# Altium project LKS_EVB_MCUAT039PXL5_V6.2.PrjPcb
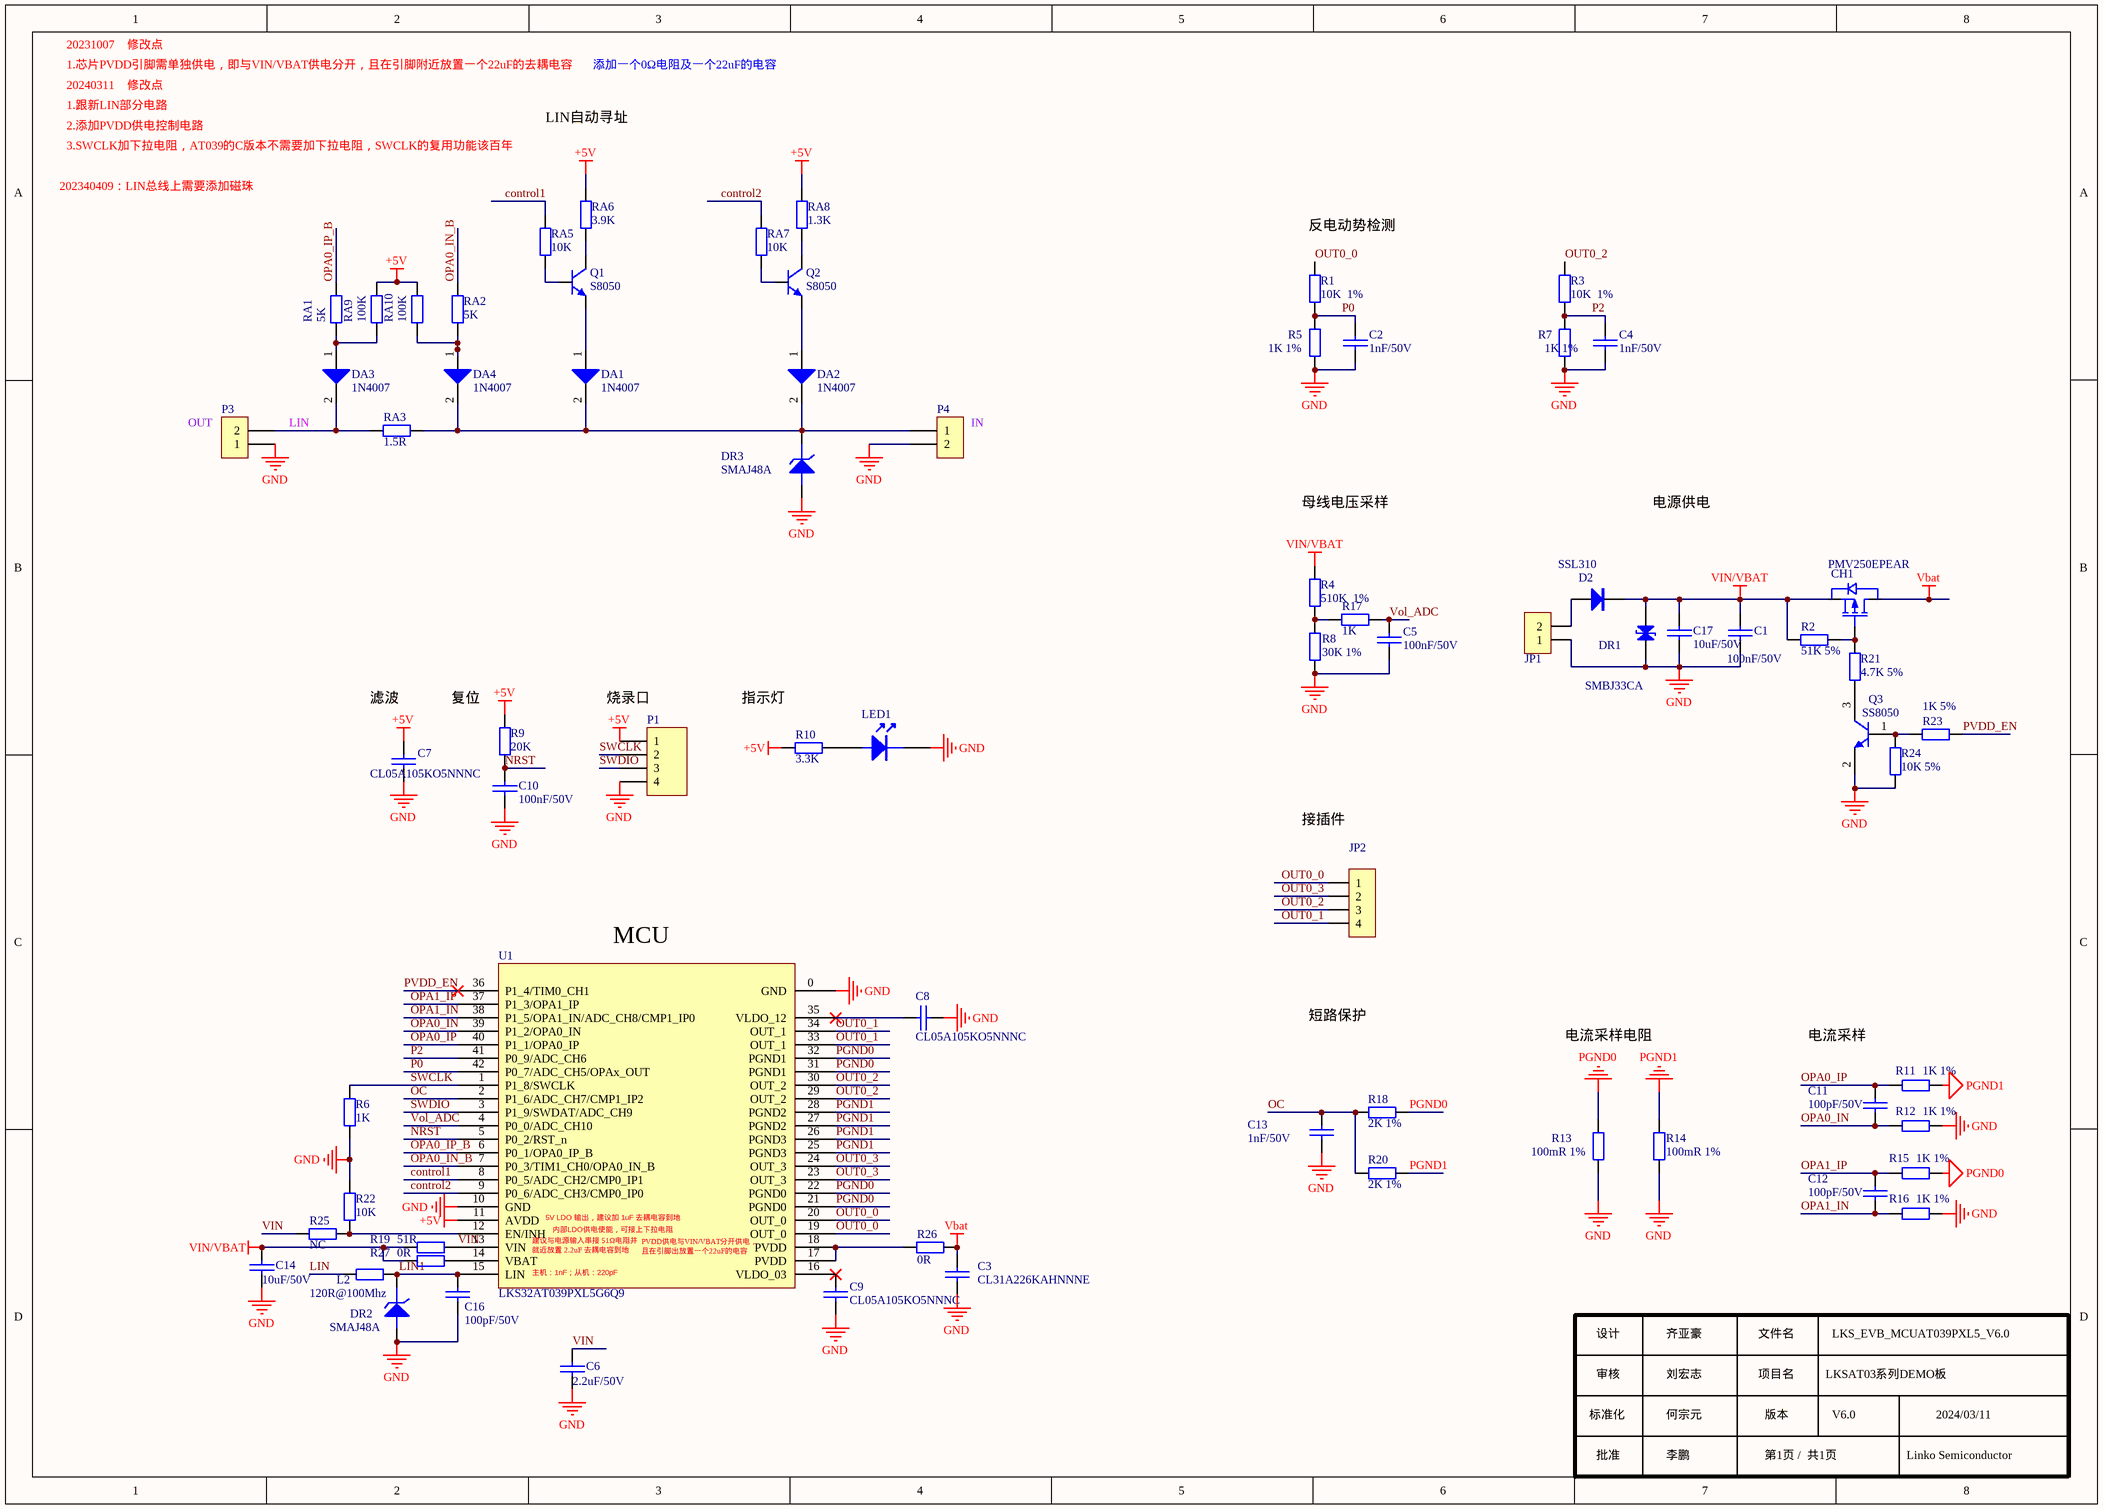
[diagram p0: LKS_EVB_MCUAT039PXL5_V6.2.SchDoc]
1 sheet, 72 parts. Net scope: global (net labels, ports and power ports of the same name join across sheets).
Board file: LKS_EVB_MCUAT039PXL5_V6.2.PcbDoc

## Sheet LKS_EVB_MCUAT039PXL5_V6.2.SchDoc
size A3; SheetNumber: 1; SheetTotal: 1

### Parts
C1  100nF/50V  [0805C]
C2  1nF/50V  [0603C]
C3  CL31A226KAHNNNE  [1206C]
C4  1nF/50V  [0603C]
C5  100nF/50V  [0603C]
C6  2.2uF/50V  [0805C]
C7  CL05A105KO5NNNC  [0402C]
C8  CL05A105KO5NNNC  [0402C]
C9  CL05A105KO5NNNC  [0402C]
C10  100nF/50V  [0603C]
C11  100pF/50V  [0603C]
C12  100pF/50V  [0603C]
C13  1nF/50V  [0603C]
C14  10uF/50V  [0805C]
C16  100pF/50V  [0603C]
C17  10uF/50V  [0805C]
CH1  PMV250EPEAR  [SOT-23]
D2  SSL310  [SMA]
DA1  1N4007  [SOD-323]
DA2  1N4007  [SOD-323]
DA3  1N4007  [SOD-323]
DA4  1N4007  [SOD-323]
DR1  SMBJ33CA  [SMB]
DR2  SMAJ48A  [SMA]
DR3  SMAJ48A  [SMA]
JP1  B2P-VH(LF)(SN)  [HT3.96-LI-2P]  (value not drawn)
JP2  HDR-1X4  [HDR 1X4]  (value not drawn)
L2  120R@100Mhz  [0603R]
LED1  LED  [LED 0603G]  (value not drawn)
P1  HDR-1X4  [HDR 1X4]  (value not drawn)
P3  1X2  [HDR 1X2]  (value not drawn)
P4  1X2  [HDR 1X2]  (value not drawn)
Q1  S8050  [SOT-23]
Q2  S8050  [SOT-23]
Q3  SS8050  [SOT-23]
R1  10K  1%  [0603R]
R2  51K 5%  [0402R]
R3  10K  1%  [0603R]
R4  510K  1%  [0603R]
R5  1K 1%  [0603R]
R6  1K  [0603R]
R7  1K 1%  [0603R]
R8  30K 1%  [0603R]
R9  20K  [0603R]
R10  3.3K  [0603R]
R11  1K 1%  [0603R]
R12  1K 1%  [0603R]
R13  100mR 1%  [1206R]
R14  100mR 1%  [1206R]
R15  1K 1%  [0603R]
R16  1K 1%  [0603R]
R17  1K  [0603R]
R18  2K 1%  [0603R]
R19  51R  [0603R]
R20  2K 1%  [0603R]
R21  4.7K 5%  [0402R]
R22  10K  [0603C _1]
R23  1K 5%  [0402R]
R24  10K 5%  [0402R]
R25  NC  [0603C _1]
R26  0R  [0603R]
R27  0R  [0603R]
RA1  5K  [0603R]
RA2  5K  [0603R]
RA3  1.5R  [0603R]
RA5  10K  [0603R]
RA6  3.9K  [0603R]
RA7  10K  [0603R]
RA8  1.3K  [0603R]
RA9  100K  [0603R]
RA10  100K  [0603R]
U1  LKS32AT039PXL5G6Q9  [QFN42-AT039PXL5]

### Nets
+5V: C7.1 P1.1 R9.1 R10.2 RA6.1 RA8.1 RA9.2 RA10.2 U1.11(AVDD)
GND: C1.2 C2.2 C3.2 C4.2 C5.2 C6.2 C7.2 C8.2 C9.2 C10.2 C13.2 C14.2 C16.2 C17.2 DR1.2(K) DR2.1 DR3.1 JP1.1 LED1.2(K) P1.4 P3.1 P4.2 Q3.2(E) R5.2 R6.1 R7.2 R8.1 R12.1 R13.1 R14.1 R16.1 R22.2 R24.2 U1.0(GND) U1.10(GND)
PGND0: R13.2 R15.1 R18.2 U1.21(PGND0) U1.22(PGND0) U1.31(PGND1) U1.32(PGND1)
PGND1: R11.1 R14.2 R20.2 U1.25(PGND3) U1.26(PGND3) U1.27(PGND2) U1.28(PGND2)
Vbat: C3.1 CH1.2(D) R26.2
VIN/VBAT: C1.1 C14.1 C17.1 CH1.3(S) D2.2(K) DR1.1(A) R2.2 R4.1 R19.1 R27.1
control1: RA5.2 U1.8(P0_5/ADC_CH2/CMP0_IP1)
control2: RA7.2 U1.9(P0_6/ADC_CH3/CMP0_IP0)
LIN: DA3.2(K) L2.1 P3.2 RA3.1
LIN1: C16.1 DR2.2 L2.2 U1.15(LIN)
NRST: C10.1 R9.2 U1.5(P0_2/RST_n)
OC: C13.1 R18.1 R20.1 U1.2(P1_6/ADC_CH7/CMP1_IP2)
OPA0_IN: C11.2 R12.2 U1.39(P1_2/OPA0_IN)
OPA0_IN_B: RA2.1 U1.7(P0_3/TIM1_CH0/OPA0_IN_B)
OPA0_IP: C11.1 R11.2 U1.40(P1_1/OPA0_IP)
OPA0_IP_B: RA1.1 U1.6(P0_1/OPA0_IP_B)
OPA1_IN: C12.2 R16.2 U1.38(P1_5/OPA1_IN/ADC_CH8/CMP1_IP0)
OPA1_IP: C12.1 R15.2 U1.37(P1_3/OPA1_IP)
OUT0_0: JP2.1 R1.1 U1.19(OUT_0) U1.20(OUT_0)
OUT0_1: JP2.4 U1.33(OUT_1) U1.34(OUT_1)
OUT0_2: JP2.3 R3.1 U1.29(OUT_2) U1.30(OUT_2)
OUT0_3: JP2.2 U1.23(OUT_3) U1.24(OUT_3)
P0: C2.1 R1.2 R5.1 U1.42(P0_7/ADC_CH5/OPAx_OUT)
P2: C4.1 R3.2 R7.1 U1.41(P0_9/ADC_CH6)
PVDD_EN: R23.2 U1.36(P1_4/TIM0_CH1)
SWCLK: P1.2 R6.2 U1.1(P1_8/SWCLK)
SWDIO: P1.3 U1.3(P1_9/SWDAT/ADC_CH9)
VIN: C6.1 R19.2 R25.2 U1.13(VIN)
Vol_ADC: C5.1 R17.1 U1.4(P0_0/ADC_CH10)
NetC8_1: C8.1 U1.35(VLDO_12)
NetC9_1: C9.1 U1.16(VLDO_03)
NetCH1_1: CH1.1(G) R2.1 R21.1
NetD2_1: D2.1(A) JP1.2
NetDA1_1: DA1.1(A) Q1.2(E)
NetDA1_2: DA1.2(K) DA2.2(K) DA4.2(K) DR3.2 P4.1 RA3.2
NetDA2_1: DA2.1(A) Q2.2(E)
NetDA3_1: DA3.1(A) RA1.2 RA9.1
NetDA4_1: DA4.1(A) RA2.2 RA10.1
NetLED1_1: LED1.1(A) R10.1
NetQ1_1: Q1.1(B) RA5.1
NetQ1_3: Q1.3(C) RA6.2
NetQ2_1: Q2.1(B) RA7.1
NetQ2_3: Q2.3(C) RA8.2
NetQ3_1: Q3.1(B) R23.1 R24.1
NetQ3_3: Q3.3(C) R21.2
NetR4_2: R4.2 R8.2 R17.2
NetR22_1: R22.1 R25.1 U1.12(EN/INH)
NetR26_1: R26.1 U1.17(PVDD) U1.18(PVDD)
NetR27_2: R27.2 U1.14(VBAT)

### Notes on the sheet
- 20231007
- 修改点
- 1.芯片PVDD引脚需单独供电，即与VIN/VBAT供电分开，且在引脚附近放置一个22uF的去耦电容
- 20240311
- 1.跟新LIN部分电路
- 添加一个0Ω电阻及一个22uF的电容
- 2.添加PVDD供电控制电路
- 3.SWCLK加下拉电阻，AT039的C版本不需要加下拉电阻，SWCLK的复用功能该百年
- LIN自动寻址
- 202340409：LIN总线上需要添加磁珠
- 母线电压采样
- 电源供电
- (near C7) 滤波
- 复位
- (near P1) 烧录口
- (near R10) 指示灯
- 短路保护
- 设计
- 审核
- 齐亚豪
- 刘宏志
- 文件名
- 项目名
- LKSAT03系列DEMO板
- LKS_EVB_MCUAT039PXL5_V6.0
- 标准化
- 批准
- 何宗元
- 李鹏
- 版本
- 第1页 /  共1页
- V6.0
- Linko Semiconductor
- 2024/03/11
- Labels drawn without touching a wire or pin: IN, MCU, OUT, 反电动势检测, 接插件, 电流采样, 电流采样电阻

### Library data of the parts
C1 C6 C14 C16 C17 = Capacitor: Capacitor --贴片电容
C2 C4 C5 C7-C9 C11-C13 = CAP: Capacitor
C3 = CAP: Capacitor / 22uF/25V / 三星
C10 = C: Capacitor
CH1 = P-MOS
D2 = 1N4148: 高速开关二极管; 版权归属: 源创客
DA1-DA4 = Diode: Default Diode
DR1 = DR: 瞬态电压抑制二极管   极性：双向 反向截止电压(Vrwm)：24V 击穿电压：26.7V 反向漏电流(Ir)：1uA 峰值脉冲电流(Ipp)@10/1000μs：15.5A 最大钳位电压：38.9V TVS瞬态抑制二极管@10/1000μs：11.3A 最大钳位电压：53.3V; 钳位电压: 24; 击穿电压: 26.7
DR2 DR3 = M_ZENER3: Zener Diode
JP1 = Header 2: 2P接插件; 版权归属: 源创客
JP2 = Header 4: 4P接插件; 版权归属: 源创客
L2 R1-R9 R11 R12 R15-R27 = Res: Resistor; Value: K
LED1 = LED: LED_Light
P1 = Header 4: Header, 4-Pin
P3 P4 = 1X2: 接口
Q1 Q2 = NPN: 三极管
Q3 = NPN: NPN Bipolar Transistor
R10 = Res: Resistor; Value: 330
R13 R14 = Res: 合金电阻Resistor; Value: K
RA1-RA3 RA5-RA10 = Res2: Resistor
U1 = LKS32AT039PXL5G6Q9: 车规芯片 03x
